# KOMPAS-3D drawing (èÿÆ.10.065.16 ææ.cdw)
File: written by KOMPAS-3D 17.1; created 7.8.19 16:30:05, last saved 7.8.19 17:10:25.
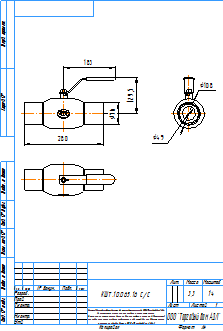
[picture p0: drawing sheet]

Sheet 1: A4, portrait

Title block, sheet 1: name: КШТ.10.065.16 С/С; material: Сталь 20  ГОСТ 1050-2013; mass: 3,3; sheets: 1; sheet format: A4; stored path: C:\Users\kka\KOMPAS_Work\Модели кранов для исследований\DN65\КШТ.10.065.16 СС.cdw

Views: Вид 1, Проекционный вид 2, Проекционный вид 3
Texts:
  kka
  adl
  Рама для чертежей
  Лит-Масса-Масштаб
  Материал-Предприятие
  Масштаб
  Изм.
  Лист
  № докум.
  Подп.
  Дата
  Лит.
  Разраб.
  Пров.
  Т.контр.
  Листов
  Внимание! Данный продукт является объектом авторского права ООО «Торговый Дом АДЛ».
  Запрещается изменение, копирование, распространение
  (в том числе путем копирования на другие сайты и ресурсы в Интернете)
  или любое иное использование информации и объектов без предварительного
  согласия правообладателя (ООО «Торговый Дом АДЛ»).
  Н.контр.
  Утв.
  ООО "Торговый дом АДЛ"
  Изменение
  Номер документа
  Подпись
  Обозначение документа
  Наименование изделия
  Масса изделия по ГОСТ 2.109-73
  Порядковый номер листа
  Общее количество листов в документе
  Характер работы, выполненной лицом, подписавшим документ
  Наименование или индекс предприятия, выпускающего документ
  Инв. № подл.
  Подп. и дата
  Взам. инв. №
  Инв. № дубл.
  Инвентарный номер подлинника по ГОСТ 2.501-68
  Подпись принявшего подлинник в отдел технической документации
  Инвентарный номер подлинника, взамен которого выпущен данный подлинник
  Инвентарный номер дубликата по ГОСТ 2.502-68
  Подпись принявшего дубликат в отдел технической документации
  Справ. №
  Перв. примен.
  Обозначение документа, взамен или на основании которого выпущен данный документ
  Обозначение документа, в котором впервые записан данный документ
  Подпись лица, копировавшего чертеж
  Обозначение формата листа
  !Рама для чертежа
Dimensions and other numbers on the sheet: 76; 280; 183; 129,5; 108; 49; 1:4; 1; 3,3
